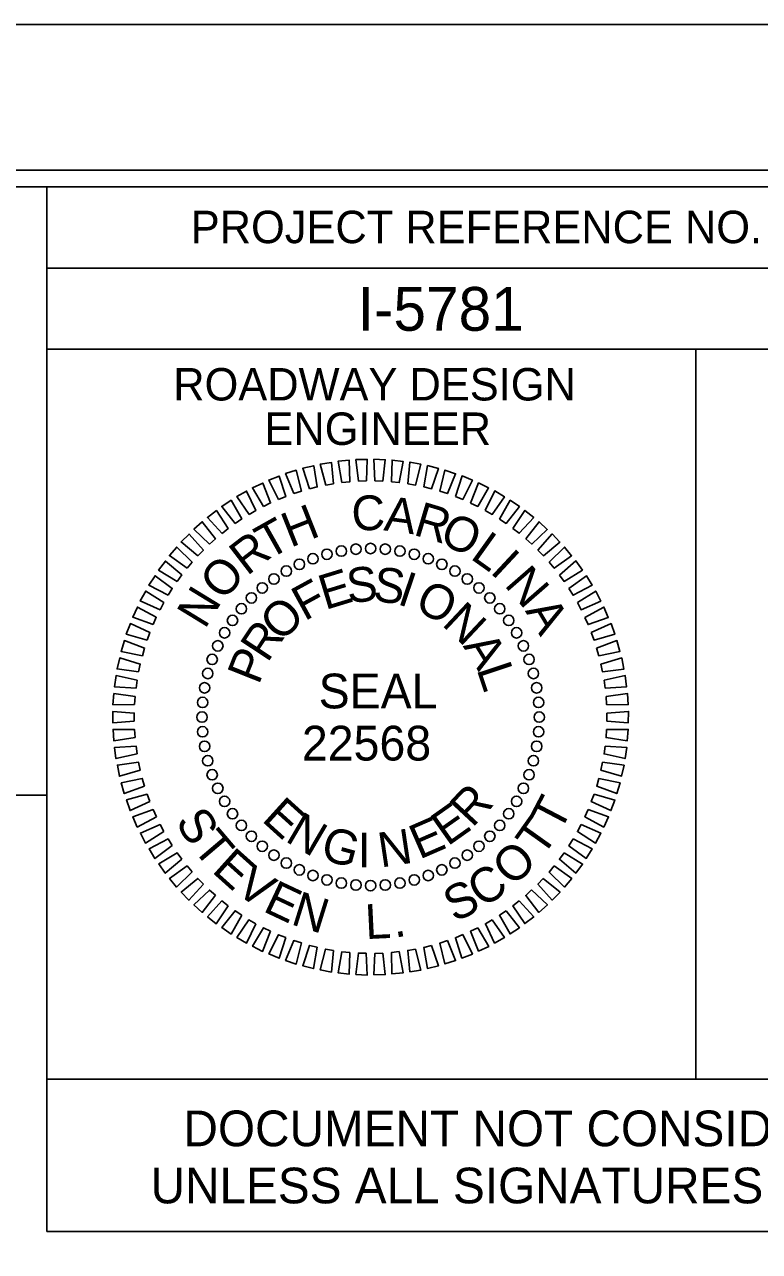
# Model space of a CAD drawing. Extents: x 2137858 to 2138172, y 2136084 to 2136289.
# Drawn here: x 2138131.33 to 2138152.47, y 2136253.7 to 2136289.01 of the extents above; entities that cross this region are included whole.
import ezdxf

# ---------------------------------------------------------------- set-up
doc = ezdxf.new("R2010")
doc.units = 0
for name, color, linetype in [('Old_Level_58', 7, 'Continuous'), ('Sheet Cutting Line CELL', 7, 'Continuous'), ('Sheet Data Field CELL', 7, 'Continuous'), ('Sheet PE Seal Cell', 7, 'Continuous'), ('Sheet Plot Border Inside CELL', 7, 'Continuous'), ('Sheet Plot Border Outside CELL', 7, 'Continuous'), ('Sheet Sticker Exception Certification CELL', 7, 'Continuous'), ('Sheet Typical CELL', 7, 'Continuous')]:
    doc.layers.add(name, color=color, linetype=linetype)

msp = doc.modelspace()

# ---------------------------------------------------------------- linework, layer by layer
at = {"layer": 'Old_Level_58'}
msp.add_lwpolyline([(2138079.453, 2136284.339), (2138131.966, 2136284.339), (2138131.966, 2136266.833), (2138079.453, 2136266.833)], close=True, dxfattribs=at)
at = {"layer": 'Sheet Cutting Line CELL'}
msp.add_line((2138172.482, 2136289.006), (2137858.136, 2136289.006), dxfattribs=at)
at = {"layer": 'Sheet PE Seal Cell'}
for points in [[(2138139.529, 2136275.647), (2138139.332, 2136276.24), (2138139.647, 2136276.312), (2138139.75, 2136275.704)], [(2138139.991, 2136275.754), (2138139.836, 2136276.359), (2138140.156, 2136276.409), (2138140.216, 2136275.795)], [(2138140.46, 2136275.828), (2138140.348, 2136276.442), (2138140.67, 2136276.47), (2138140.687, 2136275.853)], [(2138140.932, 2136275.869), (2138140.863, 2136276.489), (2138141.187, 2136276.495), (2138141.161, 2136275.878)], [(2138141.407, 2136275.877), (2138141.381, 2136276.5), (2138141.704, 2136276.483), (2138141.635, 2136275.87)], [(2138141.881, 2136275.852), (2138141.899, 2136276.476), (2138142.219, 2136276.436), (2138142.108, 2136275.829)], [(2138142.352, 2136275.794), (2138142.413, 2136276.415), (2138142.73, 2136276.353), (2138142.577, 2136275.755)], [(2138142.817, 2136275.703), (2138142.922, 2136276.318), (2138143.234, 2136276.234), (2138143.039, 2136275.649)], [(2138138.632, 2136275.339), (2138138.355, 2136275.899), (2138138.656, 2136276.014), (2138138.843, 2136275.426)], [(2138139.075, 2136275.509), (2138138.837, 2136276.086), (2138139.146, 2136276.181), (2138139.291, 2136275.581)], [(2138143.276, 2136275.58), (2138143.423, 2136276.186), (2138143.728, 2136276.081), (2138143.493, 2136275.51)], [(2138143.724, 2136275.425), (2138143.913, 2136276.02), (2138144.211, 2136275.893), (2138143.936, 2136275.341)], [(2138137.786, 2136274.909), (2138137.434, 2136275.425), (2138137.717, 2136275.581), (2138137.983, 2136275.025)], [(2138138.201, 2136275.139), (2138137.886, 2136275.678), (2138138.179, 2136275.814), (2138138.406, 2136275.241)], [(2138144.161, 2136275.239), (2138144.391, 2136275.819), (2138144.679, 2136275.672), (2138144.367, 2136275.14)], [(2138144.583, 2136275.023), (2138144.854, 2136275.586), (2138145.131, 2136275.419), (2138144.782, 2136274.91)], [(2138137.388, 2136274.651), (2138137.001, 2136275.141), (2138137.272, 2136275.317), (2138137.577, 2136274.78)], [(2138144.99, 2136274.779), (2138145.299, 2136275.321), (2138145.563, 2136275.136), (2138145.18, 2136274.652)], [(2138137.009, 2136274.366), (2138136.588, 2136274.827), (2138136.847, 2136275.022), (2138137.188, 2136274.508)], [(2138145.378, 2136274.506), (2138145.724, 2136275.026), (2138145.975, 2136274.822), (2138145.559, 2136274.367)], [(2138136.651, 2136274.055), (2138136.199, 2136274.486), (2138136.443, 2136274.698), (2138136.819, 2136274.209)], [(2138145.747, 2136274.207), (2138146.128, 2136274.702), (2138146.365, 2136274.481), (2138145.918, 2136274.056)], [(2138136.315, 2136273.72), (2138135.834, 2136274.118), (2138136.063, 2136274.346), (2138136.473, 2136273.885)], [(2138146.094, 2136273.884), (2138146.509, 2136274.35), (2138146.729, 2136274.113), (2138146.254, 2136273.72)], [(2138136.003, 2136273.362), (2138135.496, 2136273.725), (2138135.708, 2136273.969), (2138136.149, 2136273.538)], [(2138146.417, 2136273.536), (2138146.864, 2136273.973), (2138147.067, 2136273.721), (2138146.565, 2136273.362)], [(2138135.717, 2136272.983), (2138135.186, 2136273.31), (2138135.381, 2136273.568), (2138135.851, 2136273.169)], [(2138146.716, 2136273.167), (2138147.191, 2136273.571), (2138147.377, 2136273.307), (2138146.851, 2136272.983)], [(2138135.459, 2136272.585), (2138134.906, 2136272.875), (2138135.082, 2136273.146), (2138135.579, 2136272.78)], [(2138146.987, 2136272.778), (2138147.49, 2136273.148), (2138147.657, 2136272.871), (2138147.11, 2136272.585)], [(2138135.228, 2136272.17), (2138134.657, 2136272.421), (2138134.814, 2136272.703), (2138135.334, 2136272.373)], [(2138147.232, 2136272.372), (2138147.759, 2136272.706), (2138147.905, 2136272.417), (2138147.34, 2136272.17)], [(2138135.028, 2136271.74), (2138134.44, 2136271.95), (2138134.577, 2136272.243), (2138135.119, 2136271.95)], [(2138147.447, 2136271.949), (2138147.996, 2136272.245), (2138148.122, 2136271.947), (2138147.541, 2136271.74)], [(2138134.857, 2136271.297), (2138134.256, 2136271.466), (2138134.372, 2136271.768), (2138134.934, 2136271.513)], [(2138147.632, 2136271.512), (2138148.2, 2136271.769), (2138148.306, 2136271.463), (2138147.711, 2136271.297)], [(2138134.718, 2136270.844), (2138134.107, 2136270.97), (2138134.202, 2136271.279), (2138134.78, 2136271.064)], [(2138147.786, 2136271.063), (2138148.371, 2136271.28), (2138148.455, 2136270.968), (2138147.85, 2136270.844)], [(2138134.611, 2136270.382), (2138133.993, 2136270.465), (2138134.065, 2136270.78), (2138134.657, 2136270.605)], [(2138147.908, 2136270.605), (2138148.507, 2136270.78), (2138148.569, 2136270.463), (2138147.957, 2136270.381)], [(2138134.537, 2136269.913), (2138133.914, 2136269.953), (2138133.964, 2136270.272), (2138134.567, 2136270.139)], [(2138147.999, 2136270.139), (2138148.608, 2136270.272), (2138148.648, 2136269.951), (2138148.032, 2136269.913)], [(2138134.495, 2136269.44), (2138133.871, 2136269.436), (2138133.899, 2136269.758), (2138134.509, 2136269.668)], [(2138148.056, 2136269.668), (2138148.674, 2136269.758), (2138148.691, 2136269.435), (2138148.074, 2136269.44)], [(2138134.486, 2136268.966), (2138133.864, 2136268.918), (2138133.87, 2136269.242), (2138134.485, 2136269.194)], [(2138148.081, 2136269.194), (2138148.703, 2136269.241), (2138148.697, 2136268.918), (2138148.082, 2136268.965)], [(2138134.511, 2136268.492), (2138133.893, 2136268.401), (2138133.877, 2136268.724), (2138134.493, 2136268.72)], [(2138148.072, 2136268.719), (2138148.696, 2136268.723), (2138148.668, 2136268.401), (2138148.058, 2136268.491)], [(2138134.568, 2136268.021), (2138133.959, 2136267.887), (2138133.919, 2136268.208), (2138134.535, 2136268.247)], [(2138148.03, 2136268.247), (2138148.653, 2136268.207), (2138148.603, 2136267.888), (2138148, 2136268.02)], [(2138134.659, 2136267.555), (2138134.06, 2136267.379), (2138133.998, 2136267.697), (2138134.61, 2136267.778)], [(2138147.956, 2136267.778), (2138148.574, 2136267.695), (2138148.502, 2136267.38), (2138147.91, 2136267.554)], [(2138134.781, 2136267.097), (2138134.196, 2136266.88), (2138134.112, 2136267.192), (2138134.717, 2136267.316)], [(2138147.849, 2136267.316), (2138148.46, 2136267.19), (2138148.365, 2136266.881), (2138147.787, 2136267.096)], [(2138134.935, 2136266.648), (2138134.367, 2136266.391), (2138134.262, 2136266.696), (2138134.856, 2136266.862)], [(2138147.71, 2136266.862), (2138148.311, 2136266.694), (2138148.195, 2136266.392), (2138147.633, 2136266.647)], [(2138135.12, 2136266.211), (2138134.571, 2136265.915), (2138134.445, 2136266.212), (2138135.026, 2136266.419)], [(2138147.539, 2136266.419), (2138148.127, 2136266.209), (2138147.991, 2136265.916), (2138147.448, 2136266.21)], [(2138135.335, 2136265.788), (2138134.808, 2136265.454), (2138134.662, 2136265.742), (2138135.227, 2136265.989)], [(2138147.339, 2136265.989), (2138147.91, 2136265.739), (2138147.754, 2136265.456), (2138147.233, 2136265.787)], [(2138135.58, 2136265.381), (2138135.077, 2136265.011), (2138134.911, 2136265.288), (2138135.457, 2136265.574)], [(2138147.108, 2136265.575), (2138147.661, 2136265.285), (2138147.485, 2136265.014), (2138146.988, 2136265.38)], [(2138135.851, 2136264.992), (2138135.376, 2136264.588), (2138135.191, 2136264.853), (2138135.716, 2136265.176)], [(2138146.85, 2136265.177), (2138147.381, 2136264.849), (2138147.186, 2136264.591), (2138146.716, 2136264.991)], [(2138136.15, 2136264.623), (2138135.704, 2136264.187), (2138135.5, 2136264.438), (2138136.002, 2136264.797)], [(2138146.564, 2136264.798), (2138147.071, 2136264.434), (2138146.859, 2136264.19), (2138146.418, 2136264.622)], [(2138136.473, 2136264.276), (2138136.058, 2136263.81), (2138135.838, 2136264.046), (2138136.313, 2136264.439)], [(2138146.252, 2136264.44), (2138146.733, 2136264.042), (2138146.504, 2136263.813), (2138146.095, 2136264.275)], [(2138136.82, 2136263.952), (2138136.439, 2136263.458), (2138136.202, 2136263.679), (2138136.649, 2136264.104)], [(2138145.916, 2136264.105), (2138146.368, 2136263.674), (2138146.124, 2136263.462), (2138145.748, 2136263.951)], [(2138137.189, 2136263.653), (2138136.843, 2136263.134), (2138136.592, 2136263.337), (2138137.008, 2136263.793)], [(2138145.558, 2136263.794), (2138145.979, 2136263.332), (2138145.72, 2136263.138), (2138145.379, 2136263.652)], [(2138137.577, 2136263.381), (2138137.268, 2136262.838), (2138137.004, 2136263.024), (2138137.387, 2136263.507)], [(2138137.984, 2136263.136), (2138137.713, 2136262.574), (2138137.436, 2136262.74), (2138137.785, 2136263.249)], [(2138144.781, 2136263.25), (2138145.133, 2136262.735), (2138144.85, 2136262.578), (2138144.584, 2136263.135)], [(2138145.179, 2136263.508), (2138145.566, 2136263.019), (2138145.295, 2136262.843), (2138144.99, 2136263.379)], [(2138138.406, 2136262.921), (2138138.176, 2136262.34), (2138137.888, 2136262.487), (2138138.2, 2136263.019)], [(2138144.366, 2136263.02), (2138144.681, 2136262.482), (2138144.388, 2136262.345), (2138144.161, 2136262.919)], [(2138138.843, 2136262.735), (2138138.654, 2136262.14), (2138138.356, 2136262.266), (2138138.631, 2136262.819)], [(2138139.291, 2136262.58), (2138139.144, 2136261.974), (2138138.839, 2136262.079), (2138139.074, 2136262.649)], [(2138143.039, 2136262.512), (2138143.235, 2136261.92), (2138142.92, 2136261.847), (2138142.817, 2136262.455)], [(2138143.492, 2136262.651), (2138143.73, 2136262.073), (2138143.421, 2136261.979), (2138143.276, 2136262.578)], [(2138143.935, 2136262.82), (2138144.213, 2136262.261), (2138143.911, 2136262.145), (2138143.724, 2136262.733)], [(2138139.75, 2136262.457), (2138139.645, 2136261.842), (2138139.333, 2136261.925), (2138139.528, 2136262.511)], [(2138140.215, 2136262.366), (2138140.154, 2136261.745), (2138139.837, 2136261.807), (2138139.99, 2136262.404)], [(2138140.686, 2136262.308), (2138140.668, 2136261.684), (2138140.348, 2136261.724), (2138140.459, 2136262.33)], [(2138141.16, 2136262.283), (2138141.186, 2136261.659), (2138140.863, 2136261.676), (2138140.932, 2136262.289)], [(2138141.635, 2136262.291), (2138141.704, 2136261.67), (2138141.381, 2136261.665), (2138141.406, 2136262.281)], [(2138142.107, 2136262.332), (2138142.22, 2136261.718), (2138141.898, 2136261.69), (2138141.88, 2136262.306)], [(2138142.576, 2136262.406), (2138142.731, 2136261.801), (2138142.412, 2136261.751), (2138142.351, 2136262.365)]]:
    msp.add_lwpolyline(points, close=True, dxfattribs=at)
for centre in [(2138140.028, 2136273.765), (2138140.441, 2136273.856), (2138140.861, 2136273.911), (2138141.284, 2136273.93), (2138141.706, 2136273.911), (2138142.126, 2136273.856), (2138142.539, 2136273.765), (2138139.234, 2136273.475), (2138139.625, 2136273.637), (2138142.942, 2136273.637), (2138143.333, 2136273.475), (2138138.502, 2136273.053), (2138138.859, 2136273.28), (2138143.709, 2136273.28), (2138144.065, 2136273.053), (2138138.166, 2136272.795), (2138144.401, 2136272.795), (2138137.854, 2136272.509), (2138144.713, 2136272.509), (2138137.568, 2136272.197), (2138144.999, 2136272.197), (2138137.311, 2136271.862), (2138145.256, 2136271.862), (2138137.083, 2136271.505), (2138145.484, 2136271.505), (2138136.888, 2136271.129), (2138145.679, 2136271.129), (2138136.726, 2136270.739), (2138145.841, 2136270.739), (2138136.599, 2136270.335), (2138145.968, 2136270.335), (2138136.507, 2136269.922), (2138146.06, 2136269.922), (2138136.452, 2136269.502), (2138146.115, 2136269.502), (2138136.434, 2136269.08), (2138146.134, 2136269.08), (2138136.452, 2136268.657), (2138146.115, 2136268.657), (2138136.507, 2136268.238), (2138146.06, 2136268.238), (2138136.599, 2136267.825), (2138145.968, 2136267.825), (2138136.726, 2136267.421), (2138145.841, 2136267.421), (2138136.888, 2136267.03), (2138145.679, 2136267.03), (2138137.083, 2136266.655), (2138145.484, 2136266.655), (2138137.311, 2136266.298), (2138145.256, 2136266.298), (2138137.568, 2136265.962), (2138144.999, 2136265.962), (2138137.854, 2136265.65), (2138144.713, 2136265.65), (2138138.166, 2136265.364), (2138144.401, 2136265.364), (2138138.502, 2136265.107), (2138138.859, 2136264.88), (2138143.709, 2136264.88), (2138144.065, 2136265.107), (2138139.234, 2136264.684), (2138139.625, 2136264.522), (2138142.942, 2136264.522), (2138143.333, 2136264.684), (2138140.028, 2136264.395), (2138140.441, 2136264.303), (2138140.861, 2136264.248), (2138141.284, 2136264.23), (2138141.706, 2136264.248), (2138142.126, 2136264.303), (2138142.539, 2136264.395)]:
    msp.add_circle(centre, 0.15, dxfattribs=at)
at = {"layer": 'Sheet Plot Border Inside CELL'}
msp.add_lwpolyline([(2138171.642, 2136284.815), (2137860.562, 2136284.815), (2137860.562, 2136087.863), (2138171.642, 2136087.863)], close=True, dxfattribs=at)
at = {"layer": 'Sheet Plot Border Outside CELL'}
msp.add_lwpolyline([(2138172.482, 2136289.006), (2137858.136, 2136289.006), (2137858.136, 2136083.673), (2138172.482, 2136083.673)], close=True, dxfattribs=at)
at = {"layer": 'Sheet Sticker Exception Certification CELL'}
for p, q in [((2138131.966, 2136254.276), (2138131.966, 2136258.663)), ((2138131.966, 2136258.663), (2138169.309, 2136258.663)), ((2138169.309, 2136254.276), (2138131.966, 2136254.276))]:
    msp.add_line(p, q, dxfattribs=at)
at = {"layer": 'Sheet Typical CELL'}
for p, q in [((2138131.966, 2136281.997), (2138169.309, 2136281.997)), ((2138150.642, 2136279.663), (2138150.642, 2136258.673))]:
    msp.add_line(p, q, dxfattribs=at)
for points in [[(2138169.309, 2136284.339), (2137889.309, 2136284.339), (2137889.309, 2136088.339), (2138169.309, 2136088.339)], [(2138131.966, 2136284.339), (2138169.309, 2136284.339), (2138169.309, 2136279.663), (2138131.966, 2136279.663)], [(2138131.966, 2136279.663), (2138150.642, 2136279.663), (2138150.642, 2136258.663), (2138131.966, 2136258.663)], [(2138150.642, 2136279.663), (2138169.309, 2136279.663), (2138169.309, 2136258.663), (2138150.642, 2136258.663)]]:
    msp.add_lwpolyline(points, close=True, dxfattribs=at)

# ---------------------------------------------------------------- texts
at = {"layer": 'Sheet Data Field CELL'}
msp.add_text('I-5781', height=1.26, dxfattribs=at).set_placement((2138140.911, 2136280.195))
at = {"layer": 'Sheet PE Seal Cell'}
for s, rotation, p in [('C', 1.9618, (2138140.75, 2136274.44)), ('A', 352.4568, (2138141.642, 2136274.454)), ('R', 343.4093, (2138142.483, 2136274.331)), ('H', 21.601, (2138138.979, 2136273.948)), ('O', 335.2006, (2138143.22, 2136274.106)), ('T', 29.3903, (2138138.341, 2136273.591)), ('R', 37.5989, (2138137.727, 2136273.125)), ('L', 324.4755, (2138144.122, 2136273.658)), ('I', 317.0103, (2138144.693, 2136273.25)), ('O', 48.3241, (2138137.036, 2136272.392)), ('E', 16.986, (2138139.977, 2136272.157)), ('S', 5.2237, (2138140.632, 2136272.359)), ('S', 353.2648, (2138141.326, 2136272.423)), ('I', 341.3058, (2138142.018, 2136272.342)), ('N', 311.0704, (2138145.106, 2136272.875)), ('N', 58.5345, (2138136.516, 2136271.587)), ('F', 28.6639, (2138139.382, 2136271.829)), ('O', 332.5504, (2138142.506, 2136272.192)), ('O', 44.4727, (2138138.704, 2136271.207)), ('N', 316.7416, (2138143.307, 2136271.741)), ('A', 300.8599, (2138145.718, 2136272.137)), ('R', 56.5721, (2138138.316, 2136270.619)), ('P', 68.3344, (2138138.064, 2136269.982)), ('A', 301.6915, (2138143.929, 2136271.124)), ('L', 288.3556, (2138144.329, 2136270.459)), ('E', 317.8506, (2138138.122, 2136266.108)), ('R', 47.043, (2138144.21, 2136265.876)), ('T', 62.3829, (2138146.723, 2136265.725)), ('S', 302.1713, (2138135.647, 2136266.067)), ('E', 35.2807, (2138143.496, 2136265.347)), ('N', 329.6129, (2138138.794, 2136265.526)), ('E', 23.5185, (2138142.688, 2136264.974)), ('T', 54.5936, (2138146.218, 2136265.018)), ('T', 310.2847, (2138136.129, 2136265.302)), ('G', 344.6629, (2138139.802, 2136265.001)), ('I', 359.713, (2138140.912, 2136264.757)), ('N', 8.4684, (2138141.574, 2136264.75)), ('O', 43.8685, (2138145.376, 2136264.171)), ('E', 318.0739, (2138136.688, 2136264.638)), ('V', 326.0538, (2138137.349, 2136264.043)), ('C', 34.3634, (2138144.509, 2136263.563)), ('E', 334.739, (2138138.155, 2136263.507)), ('S', 26.2501, (2138143.698, 2136263.163)), ('N', 342.7189, (2138138.959, 2136263.127)), ('L', 2.8157, (2138141.146, 2136262.69)), ('.', 10.2808, (2138141.977, 2136262.727))]:
    msp.add_text(s, height=1, rotation=rotation, dxfattribs=at).set_placement(p)
for s, p in [('SEAL', (2138139.789, 2136269.33)), ('22568', (2138139.307, 2136267.83))]:
    msp.add_text(s, height=1, dxfattribs=at).set_placement(p)
at = {"layer": 'Sheet Sticker Exception Certification CELL'}
for s, p in [('DOCUMENT NOT CONSIDERED FINAL', (2138135.9, 2136256.732)), ('UNLESS ALL SIGNATURES COMPLETED', (2138134.953, 2136255.089))]:
    msp.add_text(s, height=1.02673, dxfattribs=at).set_placement(p)
at = {"layer": 'Sheet Typical CELL'}
for s, height, p in [('PROJECT REFERENCE NO.', 0.93335, (2138136.11, 2136282.715)), ('ROADWAY DESIGN', 0.93335, (2138135.606, 2136278.189)), ('ENGINEER', 0.9334, (2138138.229, 2136276.91))]:
    msp.add_text(s, height=height, dxfattribs=at).set_placement(p)

doc.saveas('drawing.dxf')
